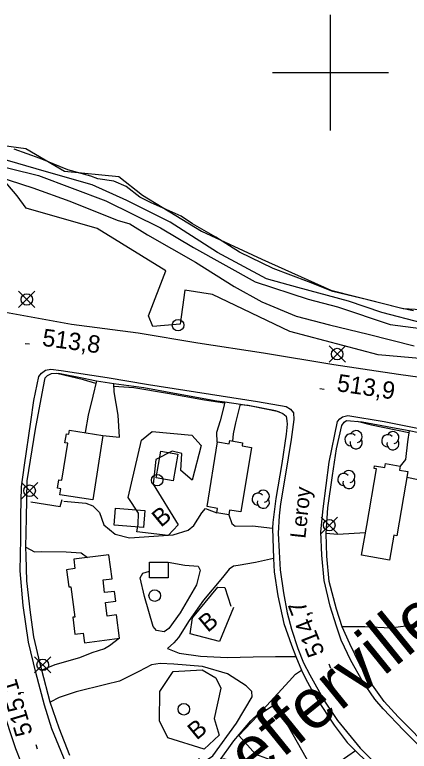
# Model space of a CAD drawing. Extents: x 347059 to 352153, y 6073752 to 6078601.
# Drawn here: x 348518.2 to 348620.4, y 6074824 to 6075015 of the extents above; entities that cross this region are included whole.
import ezdxf

# ---------------------------------------------------------------- set-up
doc = ezdxf.new("R2010")
doc.units = 0
for name, color, linetype in [('Level 1', 7, 'Continuous'), ('Level 19', 7, 'Continuous'), ('Level 2', 7, 'Continuous'), ('Level 21', 7, 'Continuous'), ('Level 22', 7, 'Continuous'), ('Level 3', 7, 'Continuous'), ('Level 31', 7, 'Continuous'), ('Level 36', 7, 'Continuous'), ('Level 37', 7, 'Continuous'), ('Level 4', 7, 'Continuous'), ('Level 41', 7, 'Continuous'), ('Level 44', 7, 'Continuous'), ('Level 61', 7, 'Continuous')]:
    doc.layers.add(name, color=color, linetype=linetype)

msp = doc.modelspace()

# ---------------------------------------------------------------- linework, layer by layer
at = {"layer": 'Level 1'}
msp.add_lwpolyline([(348509.19, 6074977.05), (348524.28, 6074973.28), (348541.73, 6074966.72), (348555.98, 6074959.71), (348564.5, 6074954.65), (348580.46, 6074945.77), (348594.19, 6074941.26), (348601.79, 6074939.3), (348615.5, 6074934.66), (348632.69, 6074932.45)], dxfattribs=at)
at = {"layer": 'Level 19'}
for points in [[(348539.38, 6074920.1), (348538.38, 6074916.08), (348537.23, 6074911.15), (348536.38, 6074906.66)], [(348541.03, 6074905.93), (348545.3, 6074905.5), (348544.95, 6074911.14), (348543.95, 6074917.2), (348543.82, 6074919.34)], [(348572.58, 6074914.61), (348572.28, 6074913.11), (348571.36, 6074909.72), (348570.46, 6074906.64), (348570.54, 6074904.17), (348570.75, 6074904.23)], [(348574.66, 6074904.45), (348574.87, 6074906.31), (348575.42, 6074909.17), (348576.64, 6074914.02)], [(348620.38, 6074907.16), (348619.93, 6074904.22), (348619.39, 6074899.65), (348618.08, 6074897.97)], [(348619.78, 6074895.05), (348622.72, 6074894.5), (348623.21, 6074900.04), (348623.75, 6074905.07), (348624.12, 6074906.51)], [(348530.85, 6074888.87), (348536.58, 6074888.39), (348538.44, 6074887.69), (348540.17, 6074885.9), (348541.23, 6074882.73), (348544.21, 6074880.33), (348547.89, 6074879.35), (348559.25, 6074880.14), (348563.13, 6074881.34), (348564.6, 6074882.56), (348566.61, 6074885.82), (348567.62, 6074886.95), (348569.12, 6074886.33), (348570.5, 6074885.84)], [(348573.61, 6074885.33), (348574.43, 6074883.08), (348575.26, 6074882.35), (348579.78, 6074882.43), (348584.98, 6074881.88)], [(348609.06, 6074880.66), (348601.81, 6074880.25), (348598.86, 6074880.48)], [(348521.06, 6074876.97), (348523.28, 6074875.74), (348525.21, 6074875.85), (348531.51, 6074875.69), (348535.34, 6074875.51), (348537.02, 6074874.27)], [(348585.18, 6074874), (348580.52, 6074873), (348576.06, 6074872.21), (348574.86, 6074872.03), (348573.76, 6074871.27), (348571.97, 6074869.1), (348567.12, 6074863.2), (348563.36, 6074857.89), (348560.62, 6074853.52), (348559.39, 6074852.11), (348557.76, 6074850.63), (348560.8, 6074849.41), (348566.27, 6074848.71), (348573.2, 6074848.33), (348579.93, 6074848.46), (348585.72, 6074848.55), (348591.02, 6074848.58)], [(348557.96, 6074873.04), (348562.21, 6074872.24), (348565.68, 6074872.05), (348566.24, 6074871.01), (348565.28, 6074867.21), (348561.05, 6074859.94), (348558.09, 6074855.83), (348556.86, 6074854.96), (348554.93, 6074855.3), (348554.04, 6074856.36), (348551.76, 6074864.14), (348550.68, 6074868.97), (348551.32, 6074870.18), (348553.09, 6074870.72)], [(348624.96, 6074857.86), (348620.12, 6074856.54), (348615.56, 6074855.97), (348608.86, 6074856.25), (348603, 6074856.24)], [(348545.34, 6074853.35), (348542.73, 6074851.36), (348541.39, 6074850.54), (348538.18, 6074849.53), (348534.95, 6074848.26), (348528.52, 6074846.43), (348525.19, 6074845.02)], [(348538.49, 6074810.49), (348542.39, 6074812.83), (348550.49, 6074817.17), (348560.04, 6074820.76), (348567.57, 6074821.55), (348569.53, 6074822.81), (348575.67, 6074831.29), (348579.7, 6074838.17), (348579.65, 6074839.48), (348578.11, 6074840.97), (348573.31, 6074844.11), (348566.81, 6074845.96), (348559.36, 6074846.59), (348555.82, 6074846.79), (348553.57, 6074846.42), (348550.3, 6074844.67), (348545.28, 6074842.22), (348541.8, 6074841.35), (348534.12, 6074839.39), (348529.65, 6074837.99), (348527.31, 6074836.78)], [(348606.51, 6074824.13), (348602.54, 6074821.36), (348595.92, 6074817.05), (348592.66, 6074814.11), (348586.12, 6074808.45), (348582.01, 6074805.63), (348576.17, 6074803.54), (348570.52, 6074802.74), (348566.05, 6074801.35), (348565.15, 6074801.8), (348564.94, 6074802.59), (348565.88, 6074807.05), (348568.54, 6074815.56), (348571.22, 6074821.53), (348574.93, 6074826.72), (348579.38, 6074831.92), (348583.42, 6074835.81), (348589.29, 6074842.19), (348590.93, 6074844.01), (348592.49, 6074845.07)]]:
    msp.add_lwpolyline(points, dxfattribs=at)
at = {"layer": 'Level 2'}
for points in [[(348667.79, 6074932.05), (348658.57, 6074933.57), (348649.4, 6074933.93), (348634.46, 6074934.07), (348623.89, 6074934.98), (348613.33, 6074937.78), (348604.64, 6074940.69), (348591.54, 6074944.28), (348583.45, 6074946.5), (348570.67, 6074953.31), (348558.41, 6074961.24), (348547.2, 6074966.83), (348538.23, 6074970.86), (348525.77, 6074974.47), (348509.36, 6074979.15)], [(348510.53, 6074974.1), (348522.85, 6074970.15), (348532.41, 6074966.65), (348544.73, 6074961.77), (348547.95, 6074960.77), (348552.61, 6074957.92), (348565.04, 6074950.86), (348575.01, 6074944.52), (348582.16, 6074940.59), (348591.12, 6074936.87), (348599.76, 6074934.61), (348609.75, 6074932.16), (348621.7, 6074929.11)], [(348539.21, 6074919.4), (348535.97, 6074920.36), (348529.06, 6074921.99)], [(348572.51, 6074914.28), (348572.49, 6074914.28), (348567.35, 6074915.03), (348557.71, 6074916.76), (348549.03, 6074918.24), (348543.87, 6074918.57)], [(348586.74, 6074911.95), (348585.76, 6074912.26), (348578.67, 6074913.64), (348576.6, 6074913.85)], [(348620.29, 6074906.57), (348610.65, 6074908.58), (348606.89, 6074909.54)]]:
    msp.add_lwpolyline(points, dxfattribs=at)
at = {"layer": 'Level 21'}
for points in [[(348512.83, 6074938.35), (348532.85, 6074934.74), (348550.12, 6074932.53), (348565.6, 6074929.94), (348582.59, 6074927.34), (348600.82, 6074924.27), (348617.58, 6074921.77), (348634.43, 6074919.43), (348651.67, 6074916.72), (348658.17, 6074915.41), (348677.38, 6074912.26), (348701.72, 6074907.64), (348717.58, 6074905.02), (348734.2, 6074902.74), (348738.26, 6074901.88), (348751.07, 6074899.82), (348764.32, 6074897.6), (348787.23, 6074894.27)], [(348531.42, 6074821.03), (348527.81, 6074829.87), (348525.86, 6074835.97), (348523.61, 6074844.44), (348521.7, 6074852.3), (348520.32, 6074861.8), (348519.54, 6074870.83), (348519.77, 6074879.11), (348519.78, 6074885.12), (348519.89, 6074892.56), (348520.69, 6074898.18), (348522.33, 6074909.45), (348523.12, 6074914.99), (348524.43, 6074921.18), (348525.09, 6074922.1), (348526.14, 6074922.82), (348527.51, 6074923.07), (348530.23, 6074922.78), (348542.08, 6074920.93), (348552.87, 6074919.1), (348562.25, 6074917.68), (348581.06, 6074914.71), (348588.48, 6074913.39), (348589.65, 6074912.71), (348590.38, 6074911.74), (348590.52, 6074910.05), (348589.8, 6074904.87), (348588.23, 6074895.39), (348587, 6074888.21), (348586.71, 6074885.04), (348586.43, 6074880.61), (348586.65, 6074875.76), (348586.99, 6074871.02), (348587.8, 6074865.09), (348588.73, 6074859.93), (348589.89, 6074855.65), (348591.52, 6074850.64), (348592.99, 6074846.98), (348594.67, 6074843.8), (348598.44, 6074837.04), (348601.79, 6074831.95), (348607.65, 6074824.83), (348611.52, 6074821)], [(348626.96, 6074821.4), (348618.92, 6074829.49), (348613.61, 6074835.05), (348611.46, 6074837.53), (348608.27, 6074842.16), (348605.28, 6074847.55), (348602.77, 6074852.81), (348601.51, 6074856.48), (348599.89, 6074861.66), (348598.32, 6074868.31), (348597.73, 6074874.88), (348597.51, 6074880.91), (348598.06, 6074886.92), (348599.65, 6074898.98), (348601.84, 6074909.51), (348602.44, 6074910.24), (348603.14, 6074910.75), (348604.45, 6074911.08), (348613.86, 6074909.53), (348622.97, 6074907.73)], [(348514.73, 6074835.74), (348518.4, 6074824.7), (348520.96, 6074818.2)]]:
    msp.add_lwpolyline(points, dxfattribs=at)
at = {"layer": 'Level 22'}
for points in [[(348532.48, 6074822.94), (348529.64, 6074830.02), (348527.31, 6074836.78), (348525.19, 6074845.02), (348524.77, 6074846.66), (348523.07, 6074853.65), (348522.22, 6074859.98), (348521.29, 6074868.21), (348521.14, 6074874.68), (348521.06, 6074876.97), (348521.18, 6074884.54), (348521.41, 6074894.18), (348523.53, 6074907.57), (348525.57, 6074918.2), (348526.01, 6074920.82), (348526.69, 6074921.45), (348527.71, 6074921.93), (348529.53, 6074922.02), (348535.65, 6074920.81), (348539.38, 6074920.1), (348543.82, 6074919.34), (348551.66, 6074918.3), (348560.5, 6074916.72), (348570.51, 6074914.92), (348572.58, 6074914.61), (348576.64, 6074914.02), (348579.41, 6074913.62), (348586.17, 6074912.19), (348587.67, 6074911.56), (348588.47, 6074910.88), (348588.69, 6074909.71), (348588.74, 6074908.85), (348588.54, 6074906.2), (348587.35, 6074898.61), (348585.79, 6074889.58), (348585.01, 6074883.31), (348584.98, 6074881.88), (348585.18, 6074874), (348585.4, 6074870.5), (348586.35, 6074864.32), (348587.91, 6074857.14), (348589.86, 6074851.56), (348591.02, 6074848.58), (348592.49, 6074845.07), (348593.56, 6074842.72), (348596.33, 6074837.68), (348600.91, 6074830.76), (348604.35, 6074826.27), (348606.51, 6074824.13), (348609.44, 6074821.25)], [(348626.52, 6074823.83), (348617.56, 6074832.95), (348613.86, 6074836.93), (348610.41, 6074841.78), (348607.56, 6074846.54), (348604.98, 6074851.89), (348603, 6074856.24), (348601.57, 6074860.83), (348599.69, 6074868.04), (348599.06, 6074874.57), (348598.86, 6074880.48), (348599.26, 6074887.11), (348600.48, 6074895.48), (348601.52, 6074902.43), (348602.94, 6074908.48), (348603.55, 6074909.37), (348604.12, 6074909.77), (348608.23, 6074909.44), (348616.06, 6074907.99), (348620.38, 6074907.16), (348622.87, 6074906.68)]]:
    msp.add_lwpolyline(points, dxfattribs=at)
at = {"layer": 'Level 3'}
for p, q in [((348520.84, 6074929.79), (348522.03, 6074929.63)), ((348597.2, 6074918.12), (348598.39, 6074917.94)), ((348600.1, 6074845.51), (348599.66, 6074846.63)), ((348524.06, 6074824.52), (348523.72, 6074825.67))]:
    msp.add_line(p, q, dxfattribs=at)
at = {"layer": 'Level 31'}
for points in [[(348541.03, 6074905.93), (348538.4, 6074889.18), (348529.88, 6074890.52), (348530.13, 6074892.09), (348529.26, 6074892.23), (348529.6, 6074894.44), (348530.39, 6074894.31), (348531.89, 6074903.89), (348531.18, 6074904), (348531.55, 6074906.35), (348532.17, 6074906.25), (348532.34, 6074907.29), (348541.03, 6074905.93)], [(348567.99, 6074887.45), (348570.75, 6074904.23), (348573.74, 6074903.74), (348573.88, 6074904.57), (348577.2, 6074904.03), (348577.07, 6074903.19), (348579.51, 6074902.79), (348576.76, 6074886.08), (348573.81, 6074886.56), (348573.61, 6074885.33), (348570.5, 6074885.84), (348570.7, 6074887), (348567.99, 6074887.45)], [(348554.8, 6074894.89), (348556, 6074901.8), (348560.47, 6074901.03), (348559.26, 6074894.11), (348554.8, 6074894.89)], [(348620.04, 6074896.57), (348617.21, 6074879.88), (348616.41, 6074880.02), (348615.32, 6074873.6), (348608.07, 6074874.83), (348609.38, 6074882.57), (348611.88, 6074897.27), (348611.32, 6074897.36), (348611.43, 6074898.02), (348614.04, 6074897.58), (348614.22, 6074898.62), (348618.08, 6074897.97), (348617.9, 6074896.94), (348620.04, 6074896.57)], [(348544.26, 6074887.02), (348551.9, 6074886.41), (348551.55, 6074882.07), (348543.92, 6074882.68), (348544.26, 6074887.02)], [(348541.46, 6074865.16), (348541.04, 6074868.47), (348543.39, 6074868.77), (348542.59, 6074874.99), (348533.44, 6074873.81), (348533.75, 6074871.37), (348531.59, 6074871.09), (348532.17, 6074866.62), (348532.71, 6074866.69), (348533.72, 6074858.82), (348533.18, 6074858.75), (348533.74, 6074854.38), (348535.9, 6074854.66), (348536.22, 6074852.17), (348545.34, 6074853.35), (348544.57, 6074859.4), (348542.15, 6074859.08), (348541.69, 6074862.6), (348544.37, 6074862.95), (348544.05, 6074865.42), (348541.46, 6074865.16)], [(348553.09, 6074873.03), (348557.96, 6074873.04), (348557.96, 6074868.96), (348553.1, 6074868.95), (348553.09, 6074873.03)]]:
    msp.add_lwpolyline(points, dxfattribs=at)
at = {"layer": 'Level 36'}
for p, q in [((348523.4, 6074939.05), (348519.17, 6074943.28)), ((348519.17, 6074939.05), (348523.4, 6074943.28)), ((348603.84, 6074924.88), (348599.61, 6074929.11)), ((348599.61, 6074924.88), (348603.84, 6074929.11)), ((348524.13, 6074889.45), (348519.9, 6074893.68)), ((348519.9, 6074889.45), (348524.13, 6074893.68)), ((348601.8, 6074880.52), (348597.57, 6074884.75)), ((348597.57, 6074880.52), (348601.8, 6074884.75)), ((348527.54, 6074844.31), (348523.31, 6074848.54)), ((348523.31, 6074844.31), (348527.54, 6074848.54))]:
    msp.add_line(p, q, dxfattribs=at)
for centre in [(348521.29, 6074941.17), (348560.48, 6074934.51), (348601.73, 6074927), (348555.08, 6074894.3), (348522.02, 6074891.57), (348599.69, 6074882.64), (348554.44, 6074864.37), (348525.43, 6074846.43), (348561.98, 6074834.91)]:
    msp.add_circle(centre, 1.5, dxfattribs=at)
at = {"layer": 'Level 37'}
msp.add_lwpolyline([(348522.35, 6074888.73), (348529.94, 6074887.47), (348530.45, 6074889.29)], dxfattribs=at)
msp.add_lwpolyline([(348522.35, 6074888.73), (348529.94, 6074887.47), (348530.45, 6074889.29)], dxfattribs=at)
at = {"layer": 'Level 4'}
for points in [[(348585.17, 6074949.24), (348576.44, 6074953.44), (348570.32, 6074957.33), (348564.25, 6074960.8), (348561.3, 6074962.79), (348553.5, 6074966.26), (348550.54, 6074967.72), (348547, 6074970.5), (348543.83, 6074971.86), (348539.72, 6074972.44), (348537.88, 6074973.1), (348531.89, 6074974.75), (348524.71, 6074977.74), (348518.04, 6074980.11)], [(348621.51, 6074938.22), (348618.15, 6074938.9), (348609.65, 6074941.1), (348600.61, 6074943.24), (348594.33, 6074945.78), (348585.17, 6074949.24)]]:
    msp.add_lwpolyline(points, dxfattribs=at)
at = {"layer": 'Level 44'}
for points in [[(348510.15, 6074981.77), (348521.05, 6074980.29), (348531.07, 6074974.46), (348545.11, 6074973.02), (348551.26, 6074968.19), (348566.56, 6074958.91), (348582.21, 6074951.58), (348600.09, 6074943.55), (348618.86, 6074938.81), (348637.55, 6074937.77), (348652.92, 6074936.15), (348670.98, 6074934.02), (348685.92, 6074932.02), (348696.01, 6074929.49), (348719.75, 6074926.9), (348736.15, 6074922.78), (348742.63, 6074923.15), (348747.83, 6074928.35), (348753.95, 6074935.54), (348759.62, 6074937.81), (348763.41, 6074938.52), (348775.01, 6074936.92)], [(348777.86, 6074902.2), (348764.97, 6074901.28), (348746.9, 6074903.64), (348718.15, 6074911.11), (348703.75, 6074916.13), (348685.83, 6074915.42), (348660.62, 6074920.79), (348638.77, 6074924.51), (348612.31, 6074926.81), (348589.48, 6074932.89), (348569.44, 6074942.48), (348562.24, 6074943.54), (348561.02, 6074934.72), (348553.99, 6074934.12), (348552.86, 6074936.93), (348557.28, 6074948.57), (348539.5, 6074959.6), (348521.11, 6074964.86), (348518.77, 6074968.02), (348513.88, 6074973.71)], [(348561.19, 6074896.8), (348561.43, 6074901.19), (348558.95, 6074901.83), (348554.74, 6074899.67), (348554.07, 6074893.27), (348560.48, 6074882.72), (348557.94, 6074880), (348549.83, 6074880.9), (348550.17, 6074882.83), (348550.27, 6074885.77), (348547.53, 6074889.78), (348551.02, 6074904.67), (348553.76, 6074906.96), (348564.07, 6074905.95), (348566.45, 6074903.28), (348564.16, 6074894.32), (348561.19, 6074896.8)], [(348574.85, 6074861.26), (348571.21, 6074852.51), (348563.59, 6074854.46), (348564.2, 6074858.59), (348570.76, 6074866.57), (348572.63, 6074866.48), (348574.15, 6074861.6)], [(348571.56, 6074840.41), (348569.86, 6074832.55), (348571.1, 6074828.18), (348567.24, 6074824.53), (348557.85, 6074827.5), (348555.71, 6074831.87), (348555.75, 6074839.55), (348559.26, 6074844.71), (348566.75, 6074845.1), (348570.25, 6074843.06), (348571.56, 6074840.41)], [(348585.77, 6074836.34), (348594.72, 6074820.41), (348593, 6074818.68), (348580.64, 6074823.17), (348576.25, 6074828.13), (348581.14, 6074833.25), (348585.77, 6074836.34)]]:
    msp.add_lwpolyline(points, dxfattribs=at)
for centre, start, end in [((348605.28, 6074904.81), 44.1154, 269.804), ((348606.63, 6074905.59), 282.2692, 149.7263), ((348614.82, 6074904.55), 44.1154, 269.804), ((348616.17, 6074905.33), 282.2692, 149.7263), ((348606.63, 6074904.02), 166.9369, 29.6212), ((348616.17, 6074903.76), 166.9369, 29.6212), ((348604.77, 6074895.24), 282.2692, 149.7263), ((348603.42, 6074894.46), 44.1154, 269.804), ((348604.77, 6074893.67), 166.9369, 29.6212), ((348581.24, 6074889.36), 44.1154, 269.804), ((348582.59, 6074890.14), 282.2692, 149.7263), ((348582.59, 6074888.57), 166.9369, 29.6212)]:
    msp.add_arc(centre, 1.57, start, end, dxfattribs=at)
at = {"layer": 'Level 61'}
for p, q in [((348600, 6074985), (348600, 6075015)), ((348585, 6075000), (348615, 6075000))]:
    msp.add_line(p, q, dxfattribs=at)

# ---------------------------------------------------------------- texts
at = {"layer": 'Level 21'}
msp.add_text('Leroy', height=4, rotation=83.8269, dxfattribs=at).set_placement((348593.47, 6074879.06))
at = {"layer": 'Level 3'}
for s, rotation, p in [('513,8', 352.4158, (348525.12, 6074929.17)), ('513,9', 351.5008, (348601.46, 6074917.43)), ('514,7', 111.5413, (348598.56, 6074849.54)), ('515,1', 106.8207, (348522.87, 6074828.67))]:
    msp.add_text(s, height=4.5, rotation=rotation, dxfattribs=at).set_placement(p)
at = {"layer": 'Level 41'}
msp.add_text('Schefferville', height=13, rotation=39, dxfattribs=at).set_placement((348556.68, 6074797.17))
at = {"layer": 'Level 44'}
for p in [(348556.04, 6074881.94), (348568.18, 6074854.68), (348565.3, 6074826.76)]:
    msp.add_text('B', height=4.5, rotation=39.568, dxfattribs=at).set_placement(p)

doc.saveas('drawing.dxf')
